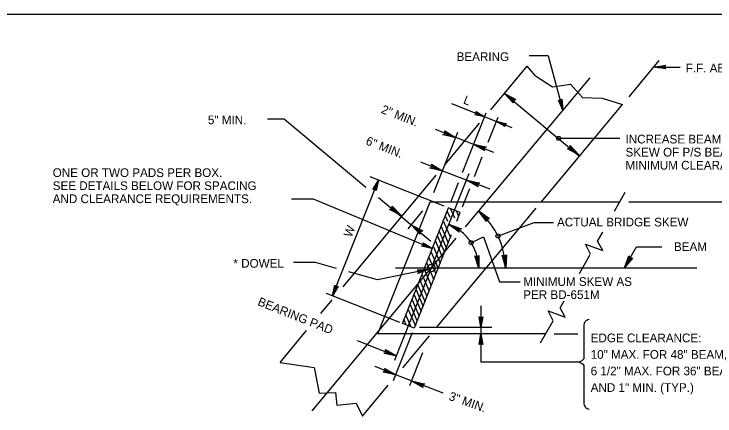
# Model space of a CAD drawing. Extents: x 639028 to 640031, y 298558 to 299746.
# Drawn here: x 639151 to 639392.4, y 298998.8 to 299137.3 of the extents above; entities that cross this region are included whole.
import ezdxf

# ---------------------------------------------------------------- set-up
doc = ezdxf.new("R2010")
doc.units = 0
doc.layers.add('1', color=7, linetype='Continuous')

msp = doc.modelspace()

# ---------------------------------------------------------------- linework, layer by layer
at = {"layer": '1'}
for p, q in [((639067.87, 299137.33), (639853.87, 299137.33)), ((639334.91, 299122.86), (639328.38, 299122.86)), ((639334.91, 299122.86), (639340.04, 299104.23)), ((639362.81, 299108.83), (639373.16, 299121.25)), ((639315.2, 299104.28), (639327.76, 299119.35)), ((639330.62, 299116.03), (639327.76, 299119.35)), ((639371.68, 299119.05), (639380.43, 299119.05)), ((639306.53, 299063.91), (639349.39, 299115.33)), ((639319.91, 299109.92), (639345.76, 299088.38)), ((639317.09, 299100.25), (639301.78, 299106.35)), ((639332.59, 299072.58), (639360.56, 299106.14)), ((639305.48, 299082.68), (639313.62, 299103.27)), ((639314.29, 299093.17), (639317.69, 299101.77)), ((639244.18, 299101.02), (639238.29, 299101.02)), ((639244.18, 299101.02), (639272.2, 299077.67)), ((639299.47, 299085.4), (639311.35, 299099.65)), ((639317.12, 299100.22), (639322.44, 299098.16)), ((639309.31, 299092.36), (639296.19, 299097.49)), ((639295.63, 299075.76), (639303.82, 299096.64)), ((639359.58, 299094.46), (639338.46, 299094.46)), ((639309.31, 299092.36), (639316.15, 299089.71)), ((639309.59, 299081.3), (639312.26, 299088.06)), ((639298.59, 299083.31), (639291.08, 299086.24)), ((639298.59, 299083.31), (639314.86, 299077.01)), ((639306.72, 299079.81), (639307.7, 299082.3)), ((639260.72, 299040.17), (639276.56, 299080)), ((639264.37, 299043.3), (639296.41, 299081.74)), ((639299.11, 299071.09), (639273.62, 299081.25)), ((639283.76, 299022.18), (639306.72, 299079.81)), ((639301.45, 299072.49), (639304.12, 299079.25)), ((639305.45, 299070.84), (639307.97, 299077.22)), ((639357.77, 299069.32), (639361.47, 299075.91)), ((639246.53, 299073.63), (639254.07, 299073.63)), ((639254.07, 299073.63), (639295.07, 299056.44)), ((639276.49, 299074.09), (639294.52, 299059.06)), ((639276.24, 299027.03), (639294.36, 299072.53)), ((639284.82, 299030.66), (639300.67, 299070.5)), ((639294.36, 299072.53), (639359.57, 299072.53)), ((639296.5, 299029.28), (639330.81, 299070.44)), ((639304.67, 299068.89), (639300.67, 299070.5)), ((639362.68, 299072.53), (639409.1, 299072.53)), ((639286.69, 299063.32), (639291.82, 299069.47)), ((639300.2, 299069.3), (639301.06, 299067.28)), ((639301.34, 299070.21), (639302.65, 299067.01)), ((639303.34, 299069.34), (639304.09, 299067.55)), ((639303.48, 299065.9), (639304.67, 299068.89)), ((639298.89, 299065.84), (639301.29, 299060.24)), ((639299.55, 299067.57), (639300.24, 299065.95)), ((639300.3, 299063.74), (639301.28, 299066.22)), ((639317.82, 299060.89), (639330.14, 299065.41)), ((639330.14, 299065.41), (639336.74, 299065.41)), ((639298.12, 299064.1), (639300.51, 299058.49)), ((639288.93, 299029.19), (639301.66, 299061.3)), ((639296.8, 299060.77), (639299.16, 299055.41)), ((639297.45, 299062.5), (639299.86, 299056.77)), ((639351.98, 299058.97), (639353.72, 299062.08)), ((639253.72, 299000.55), (639303.31, 299060.04)), ((639296.15, 299059.04), (639298.54, 299053.44)), ((639308.52, 299058.56), (639312.67, 299060.55)), ((639312.67, 299060.55), (639318.18, 299044.97)), ((639295.41, 299057.05), (639297.8, 299051.45)), ((639361.24, 299049.78), (639365.34, 299057.1)), ((639365.34, 299057.1), (639374.11, 299057.1)), ((639293.87, 299053.44), (639296.28, 299047.71)), ((639294.65, 299055.19), (639297.04, 299049.58)), ((639345.77, 299047.89), (639349.42, 299054.41)), ((639254.82, 299051.62), (639247.21, 299051.62)), ((639262.1, 299049.59), (639254.82, 299051.62)), ((639293.13, 299051.45), (639295.54, 299045.72)), ((639293.58, 299049.23), (639276.15, 299045.68)), ((639282.38, 299049.78), (639386.1, 299049.78)), ((639292.28, 299049.32), (639294.67, 299043.71)), ((639276.15, 299045.68), (639266.34, 299048.41)), ((639291.52, 299047.45), (639293.9, 299041.97)), ((639290.11, 299043.86), (639292.51, 299038.25)), ((639290.76, 299045.58), (639293.14, 299040.1)), ((639318.18, 299044.97), (639325.28, 299044.97)), ((639289.45, 299042.25), (639291.85, 299036.52)), ((639283.87, 299031.02), (639258.59, 299041.02)), ((639288.79, 299040.53), (639291.2, 299034.8)), ((639256.69, 299034.08), (639260.61, 299038.78)), ((639287.48, 299037.2), (639289.73, 299031.7)), ((639288.14, 299038.8), (639290.53, 299033.19)), ((639311.8, 299036.78), (639311.8, 299030.03)), ((639339.1, 299035.99), (639340.47, 299038.44)), ((639286.7, 299035.45), (639289.22, 299029.86)), ((639285.31, 299031.74), (639285.89, 299030.18)), ((639285.96, 299033.46), (639287.62, 299029.52)), ((639348.27, 299031.72), (639347.96, 299031.57)), ((639348.58, 299031.88), (639348.27, 299031.72)), ((639349.05, 299032.04), (639348.58, 299031.88)), ((639288.82, 299029.05), (639284.82, 299030.66)), ((639290.6, 299029.36), (639315.51, 299029.36)), ((639311.8, 299030.3), (639311.8, 299017.35)), ((639332.33, 299023.92), (639336.62, 299031.57)), ((639347.34, 299030.63), (639347.18, 299030.17)), ((639347.18, 299030.17), (639347.18, 299018.44)), ((639347.49, 299030.95), (639347.34, 299030.63)), ((639347.65, 299031.26), (639347.49, 299030.95)), ((639347.8, 299031.41), (639347.65, 299031.26)), ((639347.96, 299031.57), (639347.8, 299031.41)), ((639242.66, 299017.25), (639251.78, 299028.2)), ((639334.07, 299027.03), (639276.24, 299027.03)), ((639281.65, 299010.94), (639288.21, 299027.51)), ((639337.04, 299027.03), (639345.15, 299027.03)), ((639282.66, 299019.43), (639269.27, 299024.67)), ((639284.95, 299015.41), (639294.12, 299026.42)), ((639282.09, 299017.96), (639283.76, 299022.18)), ((639287.35, 299009.32), (639291.84, 299020.67)), ((639345.63, 299017.35), (639311.8, 299017.35)), ((639346.25, 299017.66), (639345.63, 299017.35)), ((639345.63, 299017.35), (639346.56, 299016.89)), ((639346.56, 299017.82), (639346.25, 299017.66)), ((639346.87, 299018.13), (639346.56, 299017.82)), ((639347.18, 299018.44), (639346.87, 299018.13)), ((639282.44, 299012.94), (639275.34, 299015.76)), ((639346.56, 299016.89), (639346.72, 299016.73)), ((639346.72, 299016.73), (639347.03, 299016.42)), ((639347.03, 299016.42), (639347.18, 299016.26)), ((639347.18, 299016.26), (639347.18, 299002.99)), ((639298.77, 299006.62), (639282.44, 299012.94)), ((639271.06, 298998.75), (639279.89, 299009.35)), ((639347.18, 299002.99), (639347.34, 299002.53)), ((639347.34, 299002.53), (639347.49, 299002.21)), ((639347.49, 299002.21), (639347.65, 299001.9)), ((639347.65, 299001.9), (639347.8, 299001.75)), ((639347.8, 299001.75), (639347.96, 299001.59)), ((639347.96, 299001.59), (639348.27, 299001.44)), ((639348.27, 299001.44), (639348.58, 299001.28)), ((639348.58, 299001.28), (639349.05, 299001.13))]:
    msp.add_line(p, q, dxfattribs=at)
for points in [[(639375.18, 299118.68), (639375.05, 299118.93), (639371.68, 299119.05), (639375.18, 299118.68), (639375.3, 299118.43), (639371.68, 299119.05), (639375.05, 299119.18), (639375.18, 299119.43), (639371.68, 299119.05), (639375.3, 299119.68), (639375.18, 299119.43)], [(639330.62, 299116.03), (639336.47, 299112.21), (639342.58, 299113.18), (639346.73, 299108.54), (639353.56, 299108.3), (639360.56, 299106.14)], [(639322.81, 299107.06), (639322.86, 299107.36), (639319.91, 299109.92), (639322.81, 299107.06), (639322.91, 299106.74), (639319.91, 299109.92), (639323.2, 299107.61), (639323.54, 299107.86), (639319.91, 299109.92), (639323.84, 299107.81), (639323.54, 299107.86)], [(639339.48, 299107.82), (639339.32, 299107.63), (639340.04, 299104.23), (639339.48, 299107.82), (639339.64, 299108.01), (639340.04, 299104.23), (639338.98, 299107.43), (639338.71, 299107.5), (639340.04, 299104.23), (639338.52, 299107.66), (639338.71, 299107.5)], [(639310.19, 299103.4), (639310.21, 299103.25), (639313.12, 299101.83), (639310.19, 299103.4), (639310.15, 299103.7), (639313.12, 299101.83), (639310.1, 299102.94), (639309.97, 299102.77), (639313.12, 299101.83), (639309.69, 299102.58), (639309.97, 299102.77)], [(639320.06, 299098.65), (639320.02, 299098.94), (639317.12, 299100.22), (639320.06, 299098.65), (639320.08, 299098.5), (639317.12, 299100.22), (639320.13, 299099.26), (639320.25, 299099.43), (639317.12, 299100.22), (639320.55, 299099.47), (639320.25, 299099.43)], [(639299.35, 299096.72), (639299.39, 299096.42), (639303.08, 299094.79), (639299.35, 299096.72), (639299.31, 299097.01), (639303.08, 299094.79), (639299.28, 299096.1), (639299.02, 299095.76), (639303.08, 299094.79), (639298.72, 299095.72), (639299.02, 299095.76)], [(639312.9, 299090.42), (639312.86, 299090.72), (639309.31, 299092.36), (639312.9, 299090.42), (639313.09, 299090.15), (639309.31, 299092.36), (639313.12, 299091.06), (639313.37, 299091.4), (639309.31, 299092.36), (639313.67, 299091.44), (639313.37, 299091.4)], [(639342.48, 299091.68), (639342.44, 299091.38), (639345.55, 299088.8), (639342.48, 299091.68), (639342.52, 299091.98), (639345.55, 299088.8), (639342.24, 299091.11), (639341.9, 299090.85), (639345.55, 299088.8), (639341.61, 299090.9), (639341.9, 299090.85)], [(639294.85, 299085.23), (639294.89, 299084.93), (639298.59, 299083.31), (639294.85, 299085.23), (639294.81, 299085.53), (639298.59, 299083.31), (639294.79, 299084.62), (639294.53, 299084.28), (639298.59, 299083.31), (639294.23, 299084.24), (639294.53, 299084.28)], [(639274.82, 299076.99), (639275.07, 299077.03), (639276.56, 299080), (639274.82, 299076.99), (639274.59, 299076.84), (639276.56, 299080), (639275.48, 299076.83), (639275.63, 299076.6), (639276.56, 299080), (639275.77, 299076.49), (639275.63, 299076.6)], [(639310.6, 299078.05), (639310.56, 299078.35), (639307.01, 299079.99), (639310.6, 299078.05), (639310.79, 299077.77), (639307.01, 299079.99), (639310.82, 299078.69), (639311.08, 299079.02), (639307.01, 299079.99), (639311.37, 299079.06), (639311.08, 299079.02)], [(639281.2, 299070.73), (639281.16, 299070.43), (639284.27, 299067.86), (639281.2, 299070.73), (639281.25, 299071.03), (639284.27, 299067.86), (639280.97, 299070.16), (639280.63, 299069.91), (639284.27, 299067.86), (639280.33, 299069.95), (639280.63, 299069.91)], [(639313.68, 299066.15), (639313.75, 299066.44), (639311.1, 299069.32), (639313.68, 299066.15), (639313.74, 299065.83), (639311.1, 299069.32), (639314.12, 299066.66), (639314.49, 299066.87), (639311.1, 299069.32), (639314.78, 299066.79), (639314.49, 299066.87)], [(639290.71, 299061.79), (639290.75, 299062.09), (639287.81, 299064.66), (639290.71, 299061.79), (639290.81, 299061.47), (639287.81, 299064.66), (639291.1, 299062.34), (639291.44, 299062.59), (639287.81, 299064.66), (639291.73, 299062.55), (639291.44, 299062.59)], [(639304.19, 299062.41), (639304.19, 299062.71), (639300.87, 299064.77), (639304.19, 299062.41), (639304.35, 299062.11), (639300.87, 299064.77), (639304.49, 299063.02), (639304.78, 299063.32), (639300.87, 299064.77), (639305.08, 299063.32), (639304.78, 299063.32)], [(639291.99, 299058.14), (639292.01, 299057.86), (639295.07, 299056.44), (639291.99, 299058.14), (639291.86, 299058.46), (639295.07, 299056.44), (639291.86, 299057.51), (639291.7, 299057.44), (639295.07, 299056.44), (639291.37, 299057.31), (639291.7, 299057.44)], [(639349.51, 299054.51), (639347.85, 299057.94), (639353.71, 299055.79), (639351.98, 299058.97)], [(639310.82, 299053.87), (639310.58, 299053.69), (639311.03, 299049.68), (639310.82, 299053.87), (639311.06, 299054.06), (639311.03, 299049.68), (639310.26, 299053.63), (639309.83, 299053.68), (639311.03, 299049.68), (639309.65, 299053.92), (639309.83, 299053.68)], [(639320.3, 299054.09), (639320.05, 299053.91), (639320.32, 299049.88), (639320.3, 299054.09), (639320.54, 299054.26), (639320.32, 299049.88), (639319.72, 299053.86), (639319.3, 299053.93), (639320.32, 299049.88), (639319.13, 299054.18), (639319.3, 299053.93)], [(639363.81, 299053.21), (639363.36, 299053.22), (639361.24, 299049.78), (639363.81, 299053.21), (639363.96, 299053.21), (639361.24, 299049.78), (639363.06, 299053.37), (639362.91, 299053.67), (639361.24, 299049.78), (639362.76, 299053.97), (639362.91, 299053.67)], [(639290.08, 299048.9), (639290.25, 299048.68), (639293.58, 299049.23), (639290.08, 299048.9), (639289.78, 299049.09), (639293.58, 299049.23), (639290.32, 299048.31), (639290.23, 299048.16), (639293.58, 299049.23), (639290.03, 299047.87), (639290.23, 299048.16)], [(639262.44, 299043.3), (639262.19, 299043.27), (639260.72, 299040.17), (639262.44, 299043.3), (639262.67, 299043.46), (639260.72, 299040.17), (639261.81, 299043.34), (639261.65, 299043.57), (639260.72, 299040.17), (639261.49, 299043.8), (639261.65, 299043.57)], [(639336.62, 299031.57), (639334.98, 299034.95), (639340.84, 299032.8), (639339.1, 299035.99)], [(639312.18, 299032.86), (639312.05, 299032.74), (639311.8, 299029.36), (639312.18, 299032.86), (639312.43, 299032.99), (639311.8, 299029.36), (639311.68, 299032.74), (639311.43, 299032.86), (639311.8, 299029.36), (639311.18, 299032.99), (639311.43, 299032.86)], [(639311.43, 299023.53), (639311.55, 299023.65), (639311.8, 299027.03), (639311.43, 299023.53), (639311.18, 299023.4), (639311.8, 299027.03), (639311.93, 299023.65), (639312.18, 299023.53), (639311.8, 299027.03), (639312.43, 299023.4), (639312.18, 299023.53)], [(639278.95, 299021.42), (639278.99, 299021.12), (639282.69, 299019.5), (639278.95, 299021.42), (639278.91, 299021.72), (639282.69, 299019.5), (639278.88, 299020.8), (639278.63, 299020.47), (639282.69, 299019.5), (639278.33, 299020.43), (639278.63, 299020.47)], [(639242.66, 299017.25), (639254.42, 299015.44), (639256.13, 299006.65), (639261.74, 299006.89), (639262.23, 299002.49), (639268.82, 299003.23), (639271.06, 298998.75)], [(639278.68, 299015.01), (639278.74, 299014.56), (639282.44, 299012.94), (639278.68, 299015.01), (639278.66, 299015.16), (639282.44, 299012.94), (639278.63, 299014.25), (639278.36, 299014.06), (639282.44, 299012.94), (639278.08, 299013.87), (639278.36, 299014.06)], [(639291.77, 299008.83), (639291.73, 299009.13), (639288.03, 299010.75), (639291.77, 299008.83), (639291.81, 299008.53), (639288.03, 299010.75), (639291.84, 299009.45), (639292.1, 299009.78), (639288.03, 299010.75), (639292.4, 299009.82), (639292.1, 299009.78)]]:
    msp.add_lwpolyline(points, dxfattribs=at)
for centre, radius in [((639338.54, 299094.44), 0.701), ((639317.66, 299060.8), 0.701), ((639308.42, 299058.5), 0.701), ((639294.75, 299049.78), 1.29)]:
    msp.add_circle(centre, radius, dxfattribs=at)
for radius, start, end in [(25.41, 0.1068, 49.1599), (16.2, 0.2315, 67.9252)]:
    msp.add_arc((639294.75, 299049.78), radius, start, end, dxfattribs=at)

# ---------------------------------------------------------------- texts
for s, p in [('  BEARING', (639301.19, 299121.12)), ('F.F. ABUTMENT', (639382.3, 299117.18)), ('5" MIN.', (639217.78, 299099.34)), ('INCREASE BEAM SEAT WIDTH TO ACCOMMODATE', (639361.57, 299092.7)), ('SKEW OF P/S BEAM END AND TO ACCOMMODATE', (639361.57, 299088.2)), ('MINIMUM CLEARANCES', (639361.57, 299083.7)), ('ONE OR TWO PADS PER BOX.', (639164.34, 299081.14)), ('SEE DETAILS BELOW FOR SPACING', (639164.34, 299076.64)), ('AND CLEARANCE REQUIREMENTS.', (639164.34, 299072.14)), ('ACTUAL BRIDGE SKEW', (639337.99, 299064.1)), ('  BEAM', (639376.02, 299055.63)), ('* DOWEL', (639226.56, 299049.89)), ('MINIMUM SKEW AS', (639326.36, 299043.59)), ('PER BD-651M', (639326.36, 299039.09)), ('EDGE CLEARANCE:', (639349.58, 299024.17)), ('10" MAX. FOR 48" BEAM,', (639349.58, 299018.47)), ('6 1/2" MAX. FOR 36" BEAM', (639349.58, 299012.77)), ('AND 1" MIN. (TYP.)', (639349.58, 299007.07))]:
    msp.add_text(s, height=3, dxfattribs=at).set_placement(p)
for s, rotation, p in [('L', 338.3489, (639305.48, 299106.57)), ('2" MIN.', 338.5832, (639277.19, 299103.3)), ('6" MIN.', 338.5832, (639271.88, 299092.44)), ('W', 68.3489, (639267.2, 299060.12)), ('  BEARING PAD', 338.2711, (639232.59, 299037.85)), ('3" MIN.', 340.5497, (639300.49, 299004.38))]:
    msp.add_text(s, height=3, rotation=rotation, dxfattribs=at).set_placement(p)

doc.saveas('drawing.dxf')
